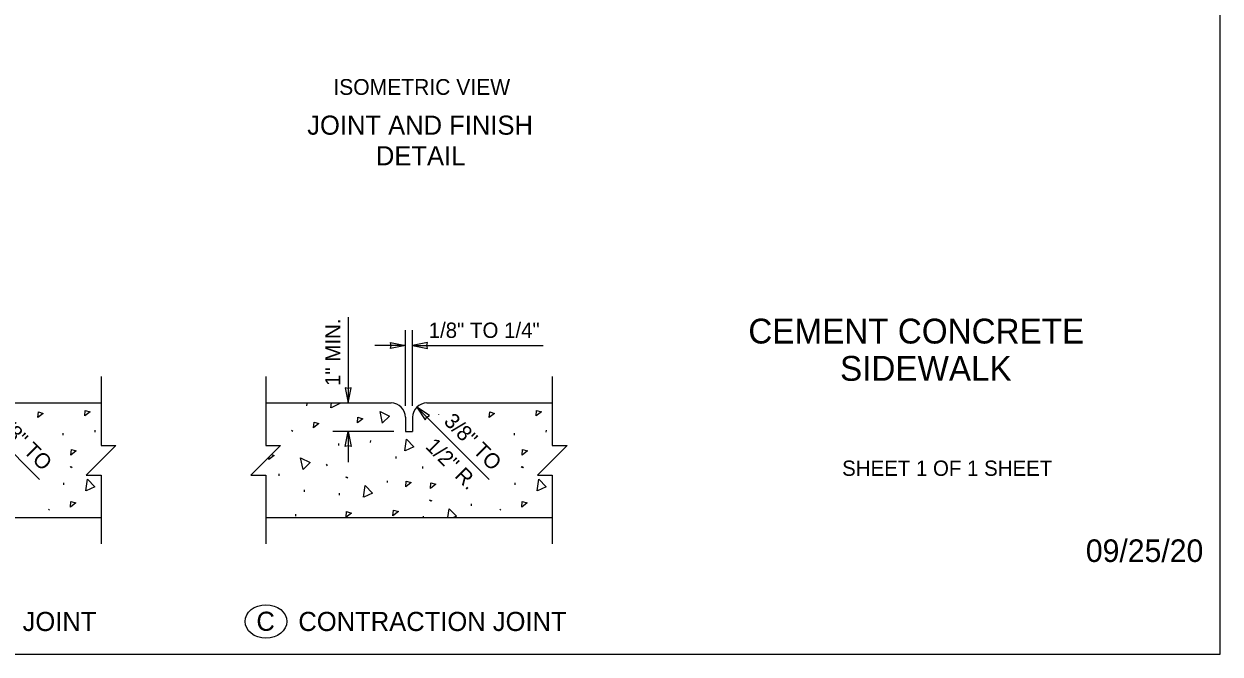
# Model space of a CAD drawing. Extents: x 99862 to 103151, y 100000 to 102076.
# Drawn here: x 101899 to 103151, y 100000 to 100659 of the extents above; entities that cross this region are included whole.
import ezdxf

# ---------------------------------------------------------------- set-up
doc = ezdxf.new("R2010")
doc.units = 0
for name, color, linetype in [('Level 1', 7, 'Continuous'), ('Level 13', 7, 'Continuous'), ('Level 15', 7, 'Continuous'), ('Level 20', 7, 'Continuous'), ('Level 6', 7, 'Continuous'), ('Level 62', 7, 'Continuous')]:
    doc.layers.add(name, color=color, linetype=linetype)

msp = doc.modelspace()

# ---------------------------------------------------------------- linework, layer by layer
at = {"layer": 'Level 1'}
msp.add_lwpolyline([(99862, 99999.5), (103151, 99999.5), (103151, 102075.5), (99862, 102075.5)], close=True, dxfattribs=at)
at = {"layer": 'Level 13'}
for p, q in [((102195.2, 100259.3), (102195.4, 100261.4)), ((102333.4, 100249.8), (102333.4, 100250.2)), ((101939.9, 100228.6), (101940.1, 100230.7)), ((101973.4, 100231.5), (101973.5, 100233.6)), ((102179.2, 100233.7), (102180.4, 100232.8)), ((102412.3, 100228.6), (102412.5, 100230.7)), ((102445.7, 100231.5), (102445.9, 100233.6)), ((102228.5, 100217.8), (102228.6, 100219.9)), ((102261.9, 100220.7), (102262, 100222.8)), ((102288.6, 100204.1), (102288.7, 100206.2)), ((101947.2, 100195.6), (101948.4, 100194.7)), ((101948.1, 100195.5), (101949.4, 100194.5)), ((102215.4, 100198.1), (102216.3, 100196.4)), ((102316.4, 100193.7), (102316.5, 100195.8)), ((102419.5, 100195.6), (102420.8, 100194.7)), ((102420.5, 100195.5), (102421.8, 100194.5)), ((101940.8, 100176.5), (101940.9, 100178.6)), ((102166, 100185.8), (102166.1, 100187.9)), ((102235.7, 100184.9), (102236.9, 100184)), ((102236.7, 100184.7), (102237.9, 100183.8)), ((102279.4, 100178.8), (102279.6, 100180.8)), ((102413.1, 100176.5), (102413.3, 100178.6)), ((102192.6, 100169.2), (102192.8, 100171.3)), ((102229.3, 100165.7), (102229.4, 100167.8)), ((102323.6, 100160.7), (102324.9, 100159.8)), ((102324.6, 100160.5), (102325.8, 100159.6)), ((102367.3, 100154.6), (102367.5, 100156.7)), ((101924.7, 100150.9), (101925.9, 100150)), ((102183.5, 100143.8), (102183.6, 100145.9)), ((102317.2, 100142.2), (102317.3, 100143.7)), ((102397, 100150.9), (102398.3, 100150))]:
    msp.add_line(p, q, dxfattribs=at)
for points in [[(101913.5, 100246.9), (101914.1, 100252.8), (101919.2, 100251.2), (101913.5, 100246.9)], [(101962.7, 100248.6), (101963.2, 100254.4), (101968.3, 100252.9), (101962.7, 100248.6)], [(102220.3, 100257.1), (102221, 100262.2)], [(102228.8, 100262.2), (102229.6, 100261.4), (102220.5, 100257.1)], [(102274.2, 100241.1), (102271.7, 100253.1), (102281.5, 100248.3), (102274.4, 100241.2)], [(102385.9, 100246.9), (102386.5, 100252.8), (102391.6, 100251.2), (102385.9, 100246.9)], [(102435, 100248.6), (102435.6, 100254.4), (102440.7, 100252.9), (102435, 100248.6)], [(102202.1, 100236.1), (102202.7, 100242), (102207.8, 100240.5), (102202.1, 100236.1)], [(102248, 100241.3), (102248.6, 100247.2), (102253.7, 100245.7), (102248, 100241.3)], [(102297.7, 100212.1), (102299.4, 100224.3), (102307, 100216.4)], [(102307, 100216.4), (102297.9, 100212.2)], [(101948, 100207.7), (101948.6, 100213.6), (101953.7, 100212.1), (101948, 100207.7)], [(102157.9, 100208.1), (102160.9, 100207.2), (102155.3, 100202.9)], [(102155.3, 100202.9), (102155.5, 100205.7)], [(102191.1, 100192.6), (102188.5, 100204.6), (102198.4, 100199.8), (102191.2, 100192.7)], [(102420.4, 100207.7), (102420.9, 100213.6), (102426, 100212.1), (102420.4, 100207.7)], [(101963.8, 100170.1), (101965.5, 100182.3), (101973.1, 100174.4), (101964, 100170.2)], [(102298.6, 100174.4), (102299.2, 100180.3), (102304.3, 100178.8), (102298.6, 100174.4)], [(102324.4, 100172.8), (102325, 100178.7), (102330.1, 100177.1), (102324.4, 100172.8)], [(102436.2, 100170.1), (102437.8, 100182.3), (102445.5, 100174.4), (102436.4, 100170.2)], [(102254.4, 100163.5), (102256.1, 100175.7), (102263.7, 100167.8), (102254.6, 100163.6)], [(101947.6, 100153.3), (101948.2, 100159.2), (101953.3, 100157.7), (101947.6, 100153.3)], [(102342.7, 100142.2), (102344, 100151.5), (102351.6, 100143.6), (102348.5, 100142.2)], [(102420, 100153.3), (102420.6, 100159.2), (102425.7, 100157.7), (102420, 100153.3)], [(102236.1, 100142.6), (102236.7, 100148.5), (102241.8, 100146.9), (102236.1, 100142.6)], [(102285.2, 100144.2), (102285.8, 100150.1), (102290.9, 100148.6), (102285.2, 100144.2)]]:
    msp.add_lwpolyline(points, dxfattribs=at)
at = {"layer": 'Level 15'}
for p, q in [((102238.3, 100351.9), (102238.3, 100262.2)), ((102298.3, 100259.2), (102298.3, 100338.2)), ((102305.8, 100259.2), (102305.8, 100338.2)), ((102298.3, 100322.2), (102266.3, 100322.2)), ((102305.8, 100322.2), (102442.4, 100322.2)), ((101839.7, 100257.8), (101915.4, 100182.1)), ((102310.2, 100257.8), (102385.9, 100182.1)), ((102286.3, 100232.2), (102222.3, 100232.2)), ((102238.3, 100232.2), (102238.3, 100200.2))]:
    msp.add_line(p, q, dxfattribs=at)
for points in [[(102298.3, 100322.2), (102282.6, 100319.1), (102283.3, 100322.2), (102282.6, 100325.3)], [(102305.8, 100322.2), (102321.5, 100319.1), (102320.8, 100322.2), (102321.5, 100325.3)], [(102238.3, 100262.2), (102241.4, 100277.9), (102238.3, 100277.2), (102235.2, 100277.9)], [(102310.2, 100257.8), (102319.1, 100244.5), (102320.8, 100247.2), (102323.5, 100248.9)], [(102238.3, 100232.2), (102241.4, 100216.5), (102238.3, 100217.2), (102235.2, 100216.5)]]:
    msp.add_lwpolyline(points, close=True, dxfattribs=at)
for points in [[(101979.7, 100289.7), (101979.7, 100217.7), (101995.1, 100217.7), (101964.2, 100186.7), (101979.7, 100186.7), (101979.7, 100114.7)], [(102152, 100289.7), (102152, 100217.7), (102167.5, 100217.7), (102136.5, 100186.7), (102152, 100186.7), (102152, 100114.7)], [(102452, 100289.7), (102452, 100217.7), (102467.5, 100217.7), (102436.5, 100186.7), (102452, 100186.7), (102452, 100114.7)]]:
    msp.add_lwpolyline(points, dxfattribs=at)
at = {"layer": 'Level 20'}
msp.add_ellipse((102152.3, 100033.6), major_axis=(-21.9, 0), ratio=0.8, dxfattribs=at)
at = {"layer": 'Level 6'}
for p, q in [((101850.3, 100262.2), (101979.7, 100262.2)), ((102152, 100262.2), (102283.3, 100262.2)), ((102320.8, 100262.2), (102452, 100262.2)), ((102298.3, 100247.2), (102298.3, 100232.2)), ((102305.8, 100247.2), (102305.8, 100232.2)), ((102298.3, 100232.2), (102305.8, 100232.2)), ((101835.3, 100142.2), (101979.7, 100142.2)), ((102152, 100142.2), (102452, 100142.2))]:
    msp.add_line(p, q, dxfattribs=at)
for centre, start, end in [((102283.3, 100247.2), 0, 90), ((102320.8, 100247.2), 90, 180)]:
    msp.add_arc(centre, 15, start, end, dxfattribs=at)

# ---------------------------------------------------------------- texts
at = {"layer": 'Level 15'}
msp.add_text('09/25/20', height=23.62, dxfattribs=at).set_placement((103010.5, 100095.8))
at = {"layer": 'Level 20'}
for s, height, p in [('ISOMETRIC VIEW', 16.5, (102222.8, 100584.4)), ('JOINT AND FINISH', 20, (102195.5, 100542.7)), ('DETAIL', 20, (102267.4, 100510.7)), ('1/8" TO 1/4"', 16, (102322.6, 100330.2)), ('EXPANSION JOINT', 20, (101734.1, 100023.6)), ('C', 20, (102142.3, 100023.8)), ('CONTRACTION JOINT', 20, (102186.2, 100023.6))]:
    msp.add_text(s, height=height, dxfattribs=at).set_placement(p)
for s, rotation, p in [('1" MIN.', 90, (102230.3, 100279.9)), ('3/8" TO', 315, (101867, 100241.8)), ('3/8" TO', 315, (102337.5, 100241.8)), ('1/2" R.', 315, (102318.3, 100215.8))]:
    msp.add_text(s, height=16, rotation=rotation, dxfattribs=at).set_placement(p)
at = {"layer": 'Level 62'}
for s, height, p in [('CEMENT CONCRETE', 26, (102657.2, 100324.3)), ('SIDEWALK', 26, (102753.2, 100285.3)), ('SHEET 1 OF 1 SHEET', 16, (102755.4, 100185.9))]:
    msp.add_text(s, height=height, dxfattribs=at).set_placement(p)

doc.saveas('drawing.dxf')
